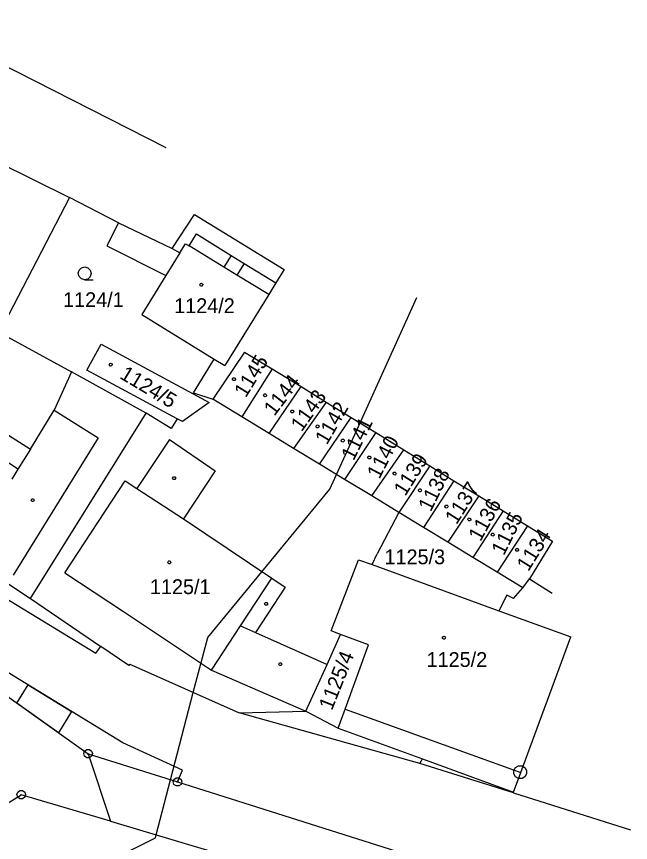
# Model space of a CAD drawing. Extents: x -806774 to -803680, y -1151731 to -1150053.
# Drawn here: x -803974.9 to -803904.5, y -1150286 to -1150191.2 of the extents above; entities that cross this region are included whole.
import ezdxf

# ---------------------------------------------------------------- set-up
doc = ezdxf.new("R2010")
doc.units = 0
for name, color, linetype in [('1', 7, 'Continuous'), ('11', 7, 'Continuous'), ('12', 7, 'Continuous'), ('13', 7, 'Continuous'), ('2', 7, 'Continuous'), ('3', 7, 'Continuous'), ('4', 7, 'Continuous'), ('5', 7, 'Continuous'), ('8', 7, 'Continuous')]:
    doc.layers.add(name, color=color, linetype=linetype)

msp = doc.modelspace()

# ---------------------------------------------------------------- linework, layer by layer
at = {"layer": '1'}
for p, q in [((-803987.32, -1150191.24), (-803957.79, -1150206.26)), ((-803982.3, -1150205.37), (-803968.85, -1150212.02)), ((-803968.85, -1150212.02), (-803976.92, -1150227.5)), ((-803963.22, -1150214.91), (-803968.85, -1150212.02)), ((-803957.07, -1150217.85), (-803954.52, -1150213.96)), ((-803954.52, -1150213.96), (-803944.24, -1150220.27)), ((-803963.22, -1150214.91), (-803964.57, -1150217.57)), ((-803963.22, -1150214.91), (-803957.07, -1150217.85)), ((-803964.57, -1150217.57), (-803957.8, -1150220.97)), ((-803944.24, -1150220.27), (-803945.18, -1150221.8)), ((-803957.8, -1150220.97), (-803960.56, -1150225.44)), ((-803945.18, -1150221.8), (-803945.99, -1150223.14)), ((-803945.99, -1150223.14), (-803951.03, -1150231.31)), ((-803960.56, -1150225.44), (-803952.26, -1150230.55)), ((-803976.82, -1150227.54), (-803968.61, -1150232.01)), ((-803966.85, -1150231.81), (-803965.2, -1150228.83)), ((-803965.2, -1150228.83), (-803954.67, -1150234.53)), ((-803948.76, -1150229.77), (-803952.4, -1150235.17)), ((-803948.76, -1150229.77), (-803945.6, -1150231.68)), ((-803954.61, -1150234.43), (-803952.26, -1150230.55)), ((-803952.26, -1150230.55), (-803951.03, -1150231.31)), ((-803960.05, -1150236.75), (-803968.61, -1150232.01)), ((-803956.49, -1150237.42), (-803966.85, -1150231.81)), ((-803945.6, -1150231.68), (-803949.07, -1150237.2)), ((-803945.6, -1150231.68), (-803942.29, -1150233.72)), ((-803945.96, -1150239.09), (-803942.29, -1150233.72)), ((-803942.29, -1150233.72), (-803939.41, -1150235.49)), ((-803954.67, -1150234.53), (-803954.61, -1150234.43)), ((-803954.67, -1150234.53), (-803952.83, -1150235.52)), ((-803954.61, -1150234.43), (-803952.4, -1150235.17)), ((-803952.83, -1150235.52), (-803955.9, -1150237.73)), ((-803949.07, -1150237.2), (-803952.4, -1150235.17)), ((-803939.41, -1150235.49), (-803943.15, -1150240.8)), ((-803939.41, -1150235.49), (-803936.54, -1150237.26)), ((-803973.34, -1150258.03), (-803960.05, -1150236.75)), ((-803957.19, -1150238.54), (-803960.05, -1150236.75)), ((-803956.49, -1150237.42), (-803957.19, -1150238.54)), ((-803955.9, -1150237.73), (-803956.49, -1150237.42)), ((-803945.96, -1150239.09), (-803949.07, -1150237.2)), ((-803940.16, -1150242.62), (-803936.54, -1150237.26)), ((-803936.54, -1150237.26), (-803933.72, -1150238.99)), ((-803943.15, -1150240.8), (-803945.96, -1150239.09)), ((-803933.72, -1150238.99), (-803937.3, -1150244.36)), ((-803933.72, -1150238.99), (-803930.49, -1150240.98)), ((-803940.16, -1150242.62), (-803943.15, -1150240.8)), ((-803934.18, -1150246.26), (-803930.49, -1150240.98)), ((-803930.49, -1150240.98), (-803927.51, -1150242.81)), ((-804001.47, -1150242.58), (-803965.84, -1150264.29)), ((-803937.3, -1150244.36), (-803940.16, -1150242.62)), ((-803927.51, -1150242.81), (-803931.06, -1150248.16)), ((-803927.51, -1150242.81), (-803924.75, -1150244.51)), ((-803934.18, -1150246.26), (-803937.3, -1150244.36)), ((-803924.75, -1150244.51), (-803928.25, -1150249.87)), ((-803924.75, -1150244.51), (-803921.91, -1150246.26)), ((-803931.06, -1150248.16), (-803934.18, -1150246.26)), ((-803921.91, -1150246.26), (-803925.44, -1150251.58)), ((-803921.91, -1150246.26), (-803919.1, -1150247.99)), ((-803931.06, -1150248.16), (-803933.58, -1150252.91)), ((-803928.25, -1150249.87), (-803931.06, -1150248.16)), ((-803919.1, -1150247.99), (-803922.58, -1150253.32)), ((-803919.1, -1150247.99), (-803916.33, -1150249.69)), ((-803925.44, -1150251.58), (-803928.25, -1150249.87)), ((-803916.33, -1150249.69), (-803919.8, -1150255.01)), ((-803916.33, -1150249.69), (-803913.44, -1150251.47)), ((-803962.74, -1150274.61), (-804001.67, -1150250.78)), ((-803922.58, -1150253.32), (-803925.44, -1150251.58)), ((-803913.44, -1150251.47), (-803916.09, -1150255.76)), ((-803934.14, -1150254.15), (-803933.58, -1150252.91)), ((-803938.84, -1150261.73), (-803935.72, -1150253.58)), ((-803935.72, -1150253.58), (-803934.14, -1150254.15)), ((-803919.8, -1150255.01), (-803922.58, -1150253.32)), ((-803934.14, -1150254.15), (-803919.6, -1150259.43)), ((-803916.86, -1150256.8), (-803919.8, -1150255.01)), ((-803916.86, -1150256.8), (-803916.09, -1150255.76)), ((-803916.09, -1150255.76), (-803913.49, -1150257.44)), ((-803976.51, -1150255.94), (-803973.34, -1150258.03)), ((-803918.68, -1150257.65), (-803919.6, -1150259.43)), ((-803917.94, -1150258.03), (-803918.68, -1150257.65)), ((-803917.94, -1150258.03), (-803916.86, -1150256.8)), ((-803973.34, -1150258.03), (-803965.24, -1150263.54)), ((-803919.6, -1150259.43), (-803911.36, -1150262.42)), ((-803939.31, -1150265.6), (-803937.75, -1150262.15)), ((-803937.75, -1150262.15), (-803938.84, -1150261.73)), ((-803934.57, -1150263.36), (-803937.75, -1150262.15)), ((-803917.08, -1150278.02), (-803911.36, -1150262.42)), ((-803937.25, -1150270.73), (-803934.57, -1150263.36)), ((-803965.84, -1150264.29), (-803965.24, -1150263.54)), ((-803962.03, -1150265.73), (-803965.24, -1150263.54)), ((-803981.13, -1150265.6), (-803966.71, -1150275.85)), ((-803961.93, -1150265.57), (-803962.03, -1150265.73)), ((-803961.93, -1150265.57), (-803949.39, -1150271.17)), ((-803941.73, -1150270.98), (-803939.31, -1150265.6)), ((-803938.05, -1150272.93), (-803937.25, -1150270.73)), ((-803949.39, -1150271.17), (-803941.73, -1150270.98)), ((-803928.65, -1150276.96), (-803949.39, -1150271.17)), ((-803938.05, -1150272.93), (-803928.38, -1150276.45)), ((-803955.88, -1150277.72), (-803962.74, -1150274.61)), ((-803966.71, -1150275.85), (-803956.46, -1150279.09)), ((-803966.71, -1150275.85), (-803964.13, -1150283.6)), ((-803928.65, -1150276.96), (-803928.38, -1150276.45)), ((-803928.38, -1150276.45), (-803917.91, -1150280.27)), ((-803917.94, -1150280.35), (-803928.65, -1150276.96)), ((-803956.46, -1150279.09), (-803955.88, -1150277.72)), ((-803917.91, -1150280.27), (-803917.08, -1150278.02)), ((-803956.46, -1150279.09), (-803906.79, -1150294.77)), ((-803917.94, -1150280.35), (-803904.51, -1150284.6)), ((-803985.68, -1150287.47), (-803974.38, -1150280.55)), ((-803964.13, -1150283.6), (-803974.38, -1150280.55)), ((-803964.13, -1150283.6), (-803909.59, -1150299.84))]:
    msp.add_line(p, q, dxfattribs=at)
at = {"layer": '11'}
msp.add_lwpolyline([(-804025, -1150309.5), (-803995, -1150300.5), (-803983.85, -1150296.45), (-803979.88, -1150295), (-803973, -1150292.5), (-803959, -1150285.5), (-803958.91, -1150285.16), (-803957.26, -1150278.83), (-803954.65, -1150268.82), (-803953, -1150262.5), (-803939, -1150245.5), (-803938.23, -1150243.8), (-803935.53, -1150237.88), (-803929, -1150223.5)], dxfattribs=at)
at = {"layer": '12'}
for p, q in [((-803956.21, -1150218.38), (-803955.55, -1150217.32)), ((-803955.55, -1150217.32), (-803955.12, -1150217.54)), ((-803951.13, -1150220), (-803955.12, -1150217.54)), ((-803956.21, -1150218.38), (-803957.8, -1150220.97)), ((-803949.65, -1150220.91), (-803951.13, -1150220)), ((-803957.8, -1150220.97), (-803960.56, -1150225.44)), ((-803945.99, -1150223.14), (-803949.65, -1150220.91)), ((-803945.99, -1150223.14), (-803951.03, -1150231.31)), ((-803960.56, -1150225.44), (-803952.26, -1150230.55)), ((-803966.85, -1150231.81), (-803965.2, -1150228.83)), ((-803965.2, -1150228.83), (-803954.67, -1150234.53)), ((-803948.76, -1150229.77), (-803952.4, -1150235.17)), ((-803948.76, -1150229.77), (-803945.6, -1150231.68)), ((-803952.26, -1150230.55), (-803951.03, -1150231.31)), ((-803956.49, -1150237.42), (-803966.85, -1150231.81)), ((-803945.6, -1150231.68), (-803949.07, -1150237.2)), ((-803945.6, -1150231.68), (-803949.07, -1150237.2)), ((-803945.6, -1150231.68), (-803942.29, -1150233.72)), ((-803945.96, -1150239.09), (-803942.29, -1150233.72)), ((-803945.96, -1150239.09), (-803942.29, -1150233.72)), ((-803942.29, -1150233.72), (-803939.41, -1150235.49)), ((-803954.67, -1150234.53), (-803952.83, -1150235.52)), ((-803952.83, -1150235.52), (-803955.9, -1150237.73)), ((-803949.07, -1150237.2), (-803952.4, -1150235.17)), ((-803939.41, -1150235.49), (-803943.15, -1150240.8)), ((-803939.41, -1150235.49), (-803943.15, -1150240.8)), ((-803939.41, -1150235.49), (-803936.54, -1150237.26)), ((-803955.9, -1150237.73), (-803956.49, -1150237.42)), ((-803945.96, -1150239.09), (-803949.07, -1150237.2)), ((-803940.16, -1150242.62), (-803936.54, -1150237.26)), ((-803940.16, -1150242.62), (-803936.54, -1150237.26)), ((-803936.54, -1150237.26), (-803933.72, -1150238.99)), ((-803943.15, -1150240.8), (-803945.96, -1150239.09)), ((-803933.72, -1150238.99), (-803937.3, -1150244.36)), ((-803933.72, -1150238.99), (-803937.3, -1150244.36)), ((-803933.72, -1150238.99), (-803930.49, -1150240.98)), ((-803940.16, -1150242.62), (-803943.15, -1150240.8)), ((-803934.18, -1150246.26), (-803930.49, -1150240.98)), ((-803934.18, -1150246.26), (-803930.49, -1150240.98)), ((-803930.49, -1150240.98), (-803927.51, -1150242.81)), ((-803937.3, -1150244.36), (-803940.16, -1150242.62)), ((-803927.51, -1150242.81), (-803931.06, -1150248.16)), ((-803927.51, -1150242.81), (-803931.06, -1150248.16)), ((-803927.51, -1150242.81), (-803924.75, -1150244.51)), ((-803934.18, -1150246.26), (-803937.3, -1150244.36)), ((-803969.37, -1150255.07), (-803962.48, -1150244.54)), ((-803962.48, -1150244.54), (-803961.14, -1150245.41)), ((-803924.75, -1150244.51), (-803928.25, -1150249.87)), ((-803924.75, -1150244.51), (-803928.25, -1150249.87)), ((-803924.75, -1150244.51), (-803921.91, -1150246.26)), ((-803961.14, -1150245.41), (-803955.76, -1150248.9)), ((-803931.06, -1150248.16), (-803934.18, -1150246.26)), ((-803921.91, -1150246.26), (-803925.44, -1150251.58)), ((-803921.91, -1150246.26), (-803925.44, -1150251.58)), ((-803921.91, -1150246.26), (-803919.1, -1150247.99)), ((-803928.25, -1150249.87), (-803931.06, -1150248.16)), ((-803919.1, -1150247.99), (-803922.58, -1150253.32)), ((-803919.1, -1150247.99), (-803922.58, -1150253.32)), ((-803919.1, -1150247.99), (-803916.33, -1150249.69)), ((-803955.76, -1150248.9), (-803945.65, -1150255.69)), ((-803925.44, -1150251.58), (-803928.25, -1150249.87)), ((-803916.33, -1150249.69), (-803919.8, -1150255.01)), ((-803916.33, -1150249.69), (-803919.8, -1150255.01)), ((-803916.33, -1150249.69), (-803913.44, -1150251.47)), ((-803922.58, -1150253.32), (-803925.44, -1150251.58)), ((-803913.44, -1150251.47), (-803916.09, -1150255.76)), ((-803913.44, -1150251.47), (-803916.09, -1150255.76)), ((-803938.84, -1150261.73), (-803935.72, -1150253.58)), ((-803935.72, -1150253.58), (-803934.14, -1150254.15)), ((-803919.8, -1150255.01), (-803922.58, -1150253.32)), ((-803934.14, -1150254.15), (-803919.6, -1150259.43)), ((-803969.37, -1150255.07), (-803962.66, -1150259.54)), ((-803949.23, -1150261.17), (-803945.65, -1150255.69)), ((-803916.86, -1150256.8), (-803919.8, -1150255.01)), ((-803916.86, -1150256.8), (-803916.09, -1150255.76)), ((-803916.09, -1150255.76), (-803913.49, -1150257.44)), ((-803962.66, -1150259.54), (-803952.55, -1150266.27)), ((-803919.6, -1150259.43), (-803911.36, -1150262.42)), ((-803952.55, -1150266.27), (-803949.23, -1150261.17)), ((-803937.75, -1150262.15), (-803938.84, -1150261.73)), ((-803934.57, -1150263.36), (-803937.75, -1150262.15)), ((-803917.08, -1150278.02), (-803911.36, -1150262.42)), ((-803937.25, -1150270.73), (-803934.57, -1150263.36)), ((-803937.25, -1150270.73), (-803917.08, -1150278.02))]:
    msp.add_line(p, q, dxfattribs=at)
at = {"layer": '13'}
for p, q in [((-803974.89, -1150270.04), (-803973.6, -1150267.96)), ((-803973.6, -1150267.96), (-803968.63, -1150271.01)), ((-803970.11, -1150273.44), (-803974.89, -1150270.04)), ((-803968.63, -1150271.01), (-803970.11, -1150273.44))]:
    msp.add_line(p, q, dxfattribs=at)
at = {"layer": '3'}
msp.add_lwpolyline([(-803967.1, -1150221.45), (-803967.48, -1150221.35), (-803967.75, -1150221.08), (-803967.85, -1150220.71), (-803967.75, -1150220.34), (-803967.48, -1150220.07), (-803967.11, -1150219.97), (-803966.74, -1150220.07), (-803966.47, -1150220.34), (-803966.37, -1150220.72), (-803966.47, -1150221.1), (-803966.74, -1150221.37), (-803967.12, -1150221.47), (-803966.12, -1150221.47)], dxfattribs=at)
at = {"layer": '4'}
for p, q in [((-803955.12, -1150217.54), (-803954.3, -1150216.2)), ((-803954.3, -1150216.2), (-803950.3, -1150218.66)), ((-803957.07, -1150217.85), (-803956.21, -1150218.38)), ((-803956.21, -1150218.38), (-803955.55, -1150217.32)), ((-803955.55, -1150217.32), (-803955.12, -1150217.54)), ((-803951.13, -1150220), (-803955.12, -1150217.54)), ((-803956.21, -1150218.38), (-803957.8, -1150220.97)), ((-803950.3, -1150218.66), (-803951.13, -1150220)), ((-803950.3, -1150218.66), (-803948.82, -1150219.57)), ((-803948.82, -1150219.57), (-803949.65, -1150220.91)), ((-803948.82, -1150219.57), (-803945.18, -1150221.8)), ((-803949.65, -1150220.91), (-803951.13, -1150220)), ((-803945.99, -1150223.14), (-803949.65, -1150220.91)), ((-803968.61, -1150232.01), (-803970.59, -1150236.41)), ((-803982.21, -1150235.3), (-803973.34, -1150240.88)), ((-803973.34, -1150240.88), (-803970.59, -1150236.41)), ((-803970.59, -1150236.41), (-803965.56, -1150239.61)), ((-803965.56, -1150239.61), (-803975.3, -1150255.36)), ((-803974.76, -1150243.18), (-803979.85, -1150239.79)), ((-803957.39, -1150239.78), (-803961.14, -1150245.41)), ((-803957.39, -1150239.78), (-803952.13, -1150243.37)), ((-803973.34, -1150240.88), (-803974.05, -1150242.03)), ((-803974.05, -1150242.03), (-803974.76, -1150243.18)), ((-803974.76, -1150243.18), (-803975.46, -1150244.34)), ((-803952.13, -1150243.37), (-803955.76, -1150248.9)), ((-803969.37, -1150255.07), (-803962.48, -1150244.54)), ((-803962.48, -1150244.54), (-803961.14, -1150245.41)), ((-803961.14, -1150245.41), (-803955.76, -1150248.9)), ((-803955.76, -1150248.9), (-803945.65, -1150255.69)), ((-803969.37, -1150255.07), (-803962.66, -1150259.54)), ((-803949.23, -1150261.17), (-803945.65, -1150255.69)), ((-803945.65, -1150255.69), (-803944.11, -1150256.73)), ((-803944.11, -1150256.73), (-803947.51, -1150261.94)), ((-803962.66, -1150259.54), (-803952.55, -1150266.27)), ((-803952.55, -1150266.27), (-803949.23, -1150261.17)), ((-803949.23, -1150261.17), (-803947.51, -1150261.94)), ((-803947.51, -1150261.94), (-803941.84, -1150264.47)), ((-803941.84, -1150264.47), (-803939.31, -1150265.6)), ((-803952.55, -1150266.27), (-803941.73, -1150270.98)), ((-803937.25, -1150270.73), (-803917.08, -1150278.02)), ((-803941.73, -1150270.98), (-803938.05, -1150272.93))]:
    msp.add_line(p, q, dxfattribs=at)
at = {"layer": '5'}
for points in [[(-803953.653, -1150221.879), (-803953.573, -1150221.942), (-803953.569, -1150222.045), (-803953.579, -1150222.107), (-803953.637, -1150222.178), (-803953.74, -1150222.204), (-803953.807, -1150222.181), (-803953.874, -1150222.114), (-803953.9, -1150222.033), (-803953.881, -1150221.953), (-803953.823, -1150221.882), (-803953.72, -1150221.856)], [(-803964.053, -1150231.049), (-803963.973, -1150231.112), (-803963.969, -1150231.215), (-803963.979, -1150231.277), (-803964.037, -1150231.348), (-803964.14, -1150231.374), (-803964.207, -1150231.351), (-803964.274, -1150231.284), (-803964.3, -1150231.203), (-803964.281, -1150231.123), (-803964.223, -1150231.052), (-803964.12, -1150231.026)], [(-803950.136, -1150232.792), (-803950.078, -1150232.709), (-803949.975, -1150232.699), (-803949.912, -1150232.704), (-803949.838, -1150232.758), (-803949.805, -1150232.859), (-803949.824, -1150232.928), (-803949.887, -1150232.998), (-803949.966, -1150233.029), (-803950.048, -1150233.016), (-803950.122, -1150232.962), (-803950.155, -1150232.861)], [(-803946.576, -1150234.642), (-803946.518, -1150234.559), (-803946.415, -1150234.549), (-803946.352, -1150234.554), (-803946.278, -1150234.608), (-803946.245, -1150234.709), (-803946.264, -1150234.778), (-803946.327, -1150234.848), (-803946.406, -1150234.879), (-803946.488, -1150234.866), (-803946.562, -1150234.812), (-803946.595, -1150234.711)], [(-803943.456, -1150236.502), (-803943.398, -1150236.419), (-803943.295, -1150236.409), (-803943.232, -1150236.414), (-803943.158, -1150236.468), (-803943.125, -1150236.569), (-803943.144, -1150236.638), (-803943.207, -1150236.708), (-803943.286, -1150236.739), (-803943.368, -1150236.726), (-803943.442, -1150236.672), (-803943.475, -1150236.571)], [(-803940.556, -1150238.212), (-803940.498, -1150238.129), (-803940.395, -1150238.119), (-803940.332, -1150238.124), (-803940.258, -1150238.178), (-803940.225, -1150238.279), (-803940.244, -1150238.348), (-803940.307, -1150238.418), (-803940.386, -1150238.449), (-803940.468, -1150238.436), (-803940.542, -1150238.382), (-803940.575, -1150238.281)], [(-803937.656, -1150239.842), (-803937.598, -1150239.759), (-803937.495, -1150239.749), (-803937.432, -1150239.754), (-803937.358, -1150239.808), (-803937.325, -1150239.909), (-803937.344, -1150239.978), (-803937.407, -1150240.048), (-803937.486, -1150240.079), (-803937.568, -1150240.066), (-803937.642, -1150240.012), (-803937.675, -1150239.911)], [(-803934.616, -1150241.782), (-803934.558, -1150241.699), (-803934.455, -1150241.689), (-803934.392, -1150241.694), (-803934.318, -1150241.748), (-803934.285, -1150241.849), (-803934.304, -1150241.918), (-803934.367, -1150241.988), (-803934.446, -1150242.019), (-803934.528, -1150242.006), (-803934.602, -1150241.952), (-803934.635, -1150241.851)], [(-803956.75, -1150244.08), (-803956.66, -1150244.23), (-803956.75, -1150244.38), (-803956.93, -1150244.38), (-803957.02, -1150244.23), (-803956.93, -1150244.08)], [(-803931.716, -1150243.632), (-803931.658, -1150243.549), (-803931.555, -1150243.539), (-803931.492, -1150243.544), (-803931.418, -1150243.598), (-803931.385, -1150243.699), (-803931.404, -1150243.768), (-803931.467, -1150243.838), (-803931.546, -1150243.869), (-803931.628, -1150243.856), (-803931.702, -1150243.802), (-803931.735, -1150243.701)], [(-803928.816, -1150245.552), (-803928.758, -1150245.469), (-803928.655, -1150245.459), (-803928.592, -1150245.464), (-803928.518, -1150245.518), (-803928.485, -1150245.619), (-803928.504, -1150245.688), (-803928.567, -1150245.758), (-803928.646, -1150245.789), (-803928.728, -1150245.776), (-803928.802, -1150245.722), (-803928.835, -1150245.621)], [(-803972.98, -1150246.61), (-803972.89, -1150246.76), (-803972.98, -1150246.91), (-803973.16, -1150246.91), (-803973.25, -1150246.76), (-803973.16, -1150246.61)], [(-803925.766, -1150247.422), (-803925.708, -1150247.339), (-803925.605, -1150247.329), (-803925.542, -1150247.334), (-803925.468, -1150247.388), (-803925.435, -1150247.489), (-803925.454, -1150247.558), (-803925.517, -1150247.628), (-803925.596, -1150247.659), (-803925.678, -1150247.646), (-803925.752, -1150247.592), (-803925.785, -1150247.491)], [(-803923.146, -1150248.892), (-803923.088, -1150248.809), (-803922.985, -1150248.799), (-803922.922, -1150248.804), (-803922.848, -1150248.858), (-803922.815, -1150248.959), (-803922.834, -1150249.028), (-803922.897, -1150249.098), (-803922.976, -1150249.129), (-803923.058, -1150249.116), (-803923.132, -1150249.062), (-803923.165, -1150248.961)], [(-803920.466, -1150250.632), (-803920.408, -1150250.549), (-803920.305, -1150250.539), (-803920.242, -1150250.544), (-803920.168, -1150250.598), (-803920.135, -1150250.699), (-803920.154, -1150250.768), (-803920.217, -1150250.838), (-803920.296, -1150250.869), (-803920.378, -1150250.856), (-803920.452, -1150250.802), (-803920.485, -1150250.701)], [(-803917.676, -1150252.382), (-803917.618, -1150252.299), (-803917.515, -1150252.289), (-803917.452, -1150252.294), (-803917.378, -1150252.348), (-803917.345, -1150252.449), (-803917.364, -1150252.518), (-803917.427, -1150252.588), (-803917.506, -1150252.619), (-803917.588, -1150252.606), (-803917.662, -1150252.552), (-803917.695, -1150252.451)], [(-803957.4, -1150253.71), (-803957.3, -1150253.73), (-803957.25, -1150253.82), (-803957.23, -1150253.88), (-803957.25, -1150253.97), (-803957.33, -1150254.04), (-803957.4, -1150254.05), (-803957.49, -1150254.02), (-803957.55, -1150253.96), (-803957.57, -1150253.88), (-803957.55, -1150253.79), (-803957.47, -1150253.72)], [(-803946.21, -1150258.51), (-803946.12, -1150258.66), (-803946.21, -1150258.81), (-803946.39, -1150258.81), (-803946.48, -1150258.66), (-803946.39, -1150258.51)], [(-803925.9, -1150262.37), (-803925.8, -1150262.39), (-803925.75, -1150262.48), (-803925.73, -1150262.54), (-803925.75, -1150262.63), (-803925.83, -1150262.7), (-803925.9, -1150262.71), (-803925.99, -1150262.68), (-803926.05, -1150262.62), (-803926.07, -1150262.54), (-803926.05, -1150262.45), (-803925.97, -1150262.38)], [(-803944.57, -1150265.42), (-803944.48, -1150265.57), (-803944.57, -1150265.72), (-803944.75, -1150265.72), (-803944.84, -1150265.57), (-803944.75, -1150265.42)]]:
    msp.add_lwpolyline(points, close=True, dxfattribs=at)
at = {"layer": '8'}
for p, q in [((-803966.83, -1150275.85), (-803966.59, -1150275.85)), ((-803917.19, -1150277.97), (-803917.09, -1150277.97)), ((-803956.58, -1150279.09), (-803956.34, -1150279.09)), ((-803974.5, -1150280.55), (-803974.26, -1150280.55))]:
    msp.add_line(p, q, dxfattribs=at)
for points in [[(-803966.56, -1150275.37), (-803966.31, -1150275.55), (-803966.21, -1150275.84), (-803966.31, -1150276.13), (-803966.56, -1150276.31), (-803966.87, -1150276.31), (-803967.12, -1150276.13), (-803967.22, -1150275.84), (-803967.12, -1150275.55), (-803966.87, -1150275.37)], [(-803916.95, -1150277.25), (-803916.61, -1150277.44), (-803916.42, -1150277.78), (-803916.42, -1150278.17), (-803916.61, -1150278.51), (-803916.95, -1150278.7), (-803917.34, -1150278.7), (-803917.68, -1150278.51), (-803917.87, -1150278.17), (-803917.87, -1150277.78), (-803917.68, -1150277.44), (-803917.34, -1150277.25)], [(-803956.31, -1150278.61), (-803956.06, -1150278.79), (-803955.96, -1150279.08), (-803956.06, -1150279.37), (-803956.31, -1150279.55), (-803956.62, -1150279.55), (-803956.87, -1150279.37), (-803956.97, -1150279.08), (-803956.87, -1150278.79), (-803956.62, -1150278.61)], [(-803974.23, -1150280.07), (-803973.98, -1150280.25), (-803973.88, -1150280.54), (-803973.98, -1150280.83), (-803974.23, -1150281.01), (-803974.54, -1150281.01), (-803974.79, -1150280.83), (-803974.89, -1150280.54), (-803974.79, -1150280.25), (-803974.54, -1150280.07)]]:
    msp.add_lwpolyline(points, close=True, dxfattribs=at)

# ---------------------------------------------------------------- texts
at = {"layer": '2'}
for s, p in [('1124/1', (-803969.587, -1150224.59)), ('1124/2', (-803956.847, -1150225.28)), ('1125/3', (-803932.724, -1150254.1)), ('1125/1', (-803959.627, -1150257.53)), ('1125/2', (-803927.897, -1150265.89))]:
    msp.add_text(s, height=1.7, dxfattribs=at).set_placement(p)
for s, rotation, p in [('1145', 58.3844, (-803948.634, -1150235.076)), ('1124/5', 329.27884, (-803963.202, -1150232.701)), ('1144', 52.54023, (-803945.361, -1150237.178)), ('1143', 54.71747, (-803942.223, -1150238.979)), ('1142', 59.7595, (-803939.332, -1150240.481)), ('1141', 63.42643, (-803936.264, -1150242.309)), ('1140', 62.73888, (-803933.32, -1150244.421)), ('1139', 57.98333, (-803930.342, -1150246.377)), ('1138', 63.42643, (-803927.424, -1150248.159)), ('1137', 57.52496, (-803924.469, -1150249.639)), ('1136', 60.96271, (-803921.719, -1150251.587)), ('1135', 63.42643, (-803919.034, -1150253.189)), ('1134', 57.98333, (-803916.232, -1150255.017)), ('1125/4', 68.18198, (-803938.748, -1150270.963))]:
    msp.add_text(s, height=1.7, rotation=rotation, dxfattribs=at).set_placement(p)

doc.saveas('drawing.dxf')
